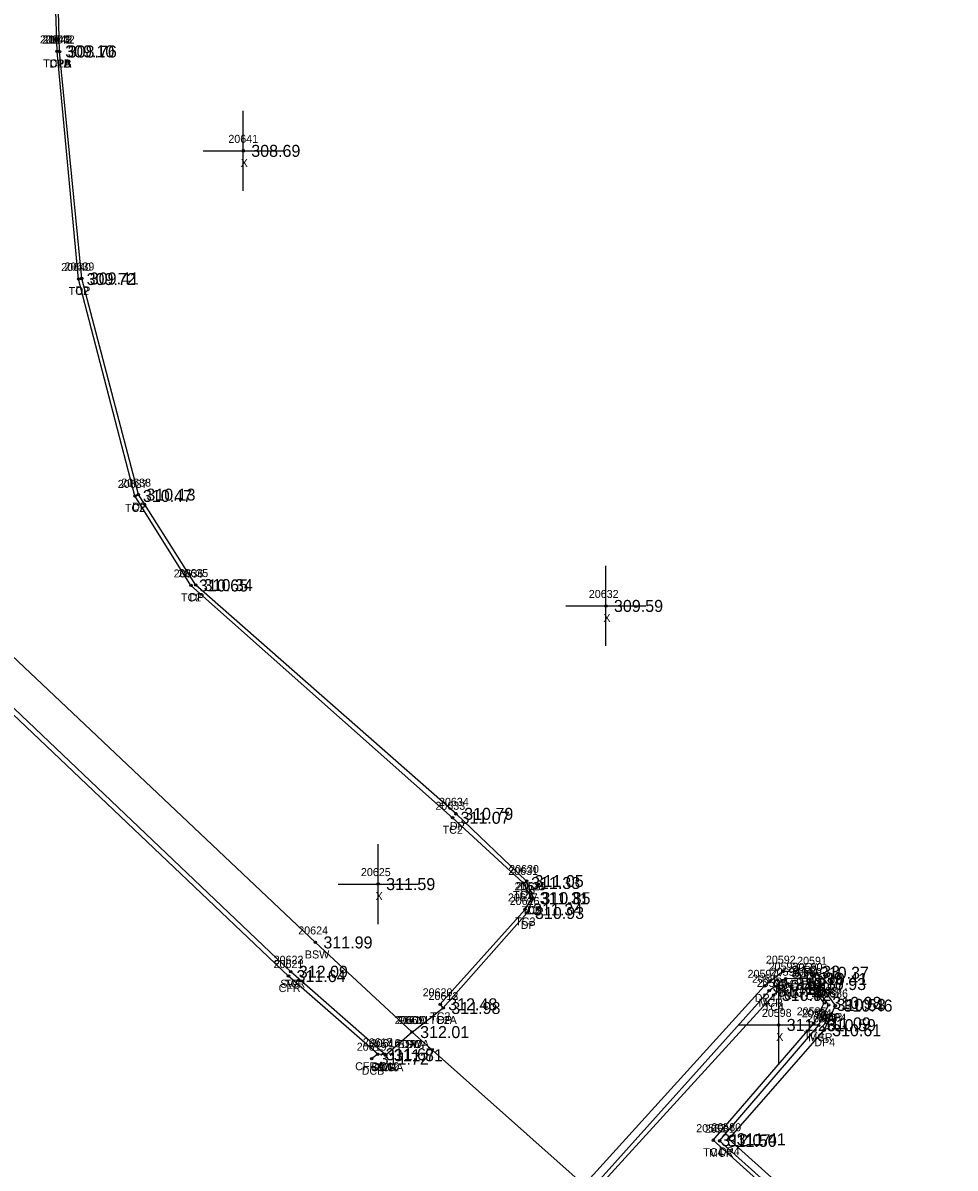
# Model space of a CAD drawing. Extents: x 1970242 to 1971082, y 803104 to 803947.
# Drawn here: x 1970776.8 to 1970893.2, y 803378.4 to 803521.5 of the extents above; entities that cross this region are included whole.
import ezdxf

# ---------------------------------------------------------------- set-up
doc = ezdxf.new("R2010")
doc.units = 0
for name, color, linetype in [('RD_DTM_BkLn2', 7, 'Continuous'), ('RD_EX_Conc', 7, 'Continuous'), ('RD_EX_Conc_txCode', 7, 'Continuous'), ('RD_EX_Driveway', 7, 'Continuous'), ('RD_EX_Driveway_txCode', 7, 'Continuous'), ('RD_EX_Misc', 7, 'Continuous'), ('RD_EX_Misc_txCode', 7, 'Continuous'), ('RD_EX_TX_Conc_ELEV', 7, 'Continuous'), ('RD_EX_TX_Driveway_ELEV', 7, 'Continuous'), ('RD_EX_TX_Misc_ELEV', 7, 'Continuous'), ('RD_SMD_Locator', 7, 'Continuous')]:
    doc.layers.add(name, color=color, linetype=linetype)

msp = doc.modelspace()

# ---------------------------------------------------------------- linework, layer by layer
at = {"layer": 'RD_DTM_BkLn2'}
for points in [[(1970781.1, 803517.91), (1970779.46, 803567.03), (1970782.19, 803572.38), (1970789.89, 803580.76), (1970789.6, 803581.03), (1970802.13, 803596.2), (1970803.32, 803597.02), (1970815.2, 803609.32), (1970835.61, 803622.91), (1970852.19, 803631.84), (1970860.32, 803643.91), (1970861.29, 803649.13), (1970859.64, 803653.18), (1970857.32, 803654.93)], [(1970822.14, 803392.47), (1970810.28, 803402.9), (1970754.12, 803456.32), (1970718.38, 803492.24), (1970714.88, 803495.79), (1970706.38, 803506.76), (1970696.99, 803522.32), (1970690.55, 803536.74), (1970687.04, 803546.39), (1970686.42, 803550.35), (1970686.87, 803560.28)], [(1970829.33, 803398.37), (1970828.94, 803398.83), (1970839.54, 803410.68), (1970840.37, 803412.09), (1970839.29, 803413.99), (1970830.48, 803422.14), (1970797.81, 803451.17), (1970790.81, 803462.36), (1970783.78, 803489.46), (1970781.1, 803517.91)], [(1970979.45, 803348.6), (1970975.44, 803343.74), (1970974.92, 803342.04), (1970975.83, 803340.42), (1970980.81, 803335.86), (1970962.06, 803319.23), (1970959.6, 803321.58), (1970957.93, 803322.04), (1970955.92, 803321.12), (1970943.88, 803309.62), (1970934.75, 803317.27), (1970863.04, 803381.85), (1970875.59, 803396.45), (1970876.91, 803399.01), (1970875, 803401.36), (1970872.33, 803401.4), (1970870.6, 803400), (1970848.18, 803375.38), (1970847.84, 803375.76)]]:
    msp.add_lwpolyline(points, dxfattribs=at)
at = {"layer": 'RD_EX_Conc'}
for points in [[(1970822.14, 803392.47), (1970810.28, 803402.9), (1970754.12, 803456.32), (1970718.38, 803492.24), (1970721.52, 803495.16)], [(1970825.43, 803395.36), (1970813.35, 803406.56), (1970757.19, 803459.64), (1970721.52, 803495.16)], [(1970821.14, 803392.59), (1970809.99, 803402.36), (1970753.68, 803455.87), (1970717.79, 803491.63)], [(1970979.04, 803348.83), (1970974.85, 803344.11), (1970974.24, 803342.07), (1970975.36, 803339.91), (1970979.77, 803335.89), (1970962.36, 803320.13), (1970959.86, 803322.22), (1970957.77, 803322.59), (1970955.64, 803321.59), (1970943.94, 803310.25), (1970935.16, 803317.85), (1970863.83, 803381.77), (1970876.22, 803396.22), (1970877.45, 803398.76), (1970875.12, 803402), (1970872.08, 803402.04), (1970870.03, 803400.53), (1970847.84, 803375.76)], [(1970847.44, 803368.09), (1970847.23, 803370.61), (1970846.91, 803376.25), (1970825.43, 803395.36), (1970822.14, 803392.47), (1970821.14, 803392.59), (1970820.38, 803392.03)]]:
    msp.add_lwpolyline(points, dxfattribs=at)
at = {"layer": 'RD_EX_Driveway'}
for points in [[(1970781.41, 803517.89), (1970780.19, 803566.79), (1970783.09, 803572.02), (1970790.56, 803580.4), (1970803.75, 803596.41), (1970815.3, 803608.83), (1970835.93, 803622.28), (1970852.1, 803631.42), (1970860.94, 803643.71), (1970861.75, 803649.17), (1970862.81, 803650.51), (1970861.9, 803654.38), (1970859.56, 803656.74), (1970855.07, 803659.55), (1970853.81, 803659.78), (1970849.95, 803660.12)], [(1970825.43, 803395.36), (1970829.33, 803398.37), (1970839.78, 803410.24), (1970840.58, 803412.09), (1970839.73, 803414.23), (1970830.93, 803422.63), (1970798.4, 803451.22), (1970791.24, 803462.52), (1970784.17, 803489.53), (1970781.41, 803517.89)], [(1970978.49, 803349.37), (1970974.36, 803344.54), (1970973.43, 803342.01), (1970974.82, 803339.34), (1970978.6, 803335.88), (1970962.13, 803321.3), (1970960.21, 803322.85), (1970957.7, 803323.38), (1970955.12, 803322.32), (1970943.79, 803311.55), (1970935.6, 803318.56), (1970864.97, 803381.97), (1970876.89, 803395.59), (1970878.3, 803398.67), (1970875.35, 803402.77), (1970871.74, 803402.91), (1970869.45, 803401.14), (1970846.9, 803376.22)]]:
    msp.add_lwpolyline(points, dxfattribs=at)
at = {"layer": 'RD_EX_Misc'}
for p, q in [((1970804.34, 803500.48), (1970804.34, 803510.48)), ((1970799.34, 803505.48), (1970809.34, 803505.48)), ((1970849.64, 803443.61), (1970849.64, 803453.61)), ((1970844.64, 803448.61), (1970854.64, 803448.61)), ((1970821.19, 803408.85), (1970821.19, 803418.85)), ((1970816.19, 803413.85), (1970826.19, 803413.85)), ((1970871.22, 803391.26), (1970871.22, 803401.26)), ((1970866.22, 803396.26), (1970876.22, 803396.26))]:
    msp.add_line(p, q, dxfattribs=at)
at = {"layer": 'RD_SMD_Locator'}
for centre in [(1970781.1, 803517.91), (1970781.1, 803517.91), (1970781.41, 803517.89), (1970781.41, 803517.89), (1970804.34, 803505.48), (1970784.17, 803489.53), (1970783.78, 803489.46), (1970790.81, 803462.36), (1970791.24, 803462.52), (1970797.81, 803451.17), (1970798.4, 803451.22), (1970849.64, 803448.61), (1970830.93, 803422.63), (1970830.48, 803422.14), (1970821.19, 803413.85), (1970839.29, 803413.99), (1970839.73, 803414.23), (1970840.37, 803412.09), (1970840.58, 803412.09), (1970839.54, 803410.68), (1970839.78, 803410.24), (1970813.35, 803406.56), (1970809.99, 803402.36), (1970810.28, 803402.9), (1970810.28, 803402.9), (1970871.74, 803402.91), (1970875.35, 803402.77), (1970869.45, 803401.14), (1970872.08, 803402.04), (1970872.33, 803401.4), (1970875, 803401.36), (1970875.12, 803402), (1970870.03, 803400.53), (1970870.6, 803400), (1970828.94, 803398.83), (1970829.33, 803398.37), (1970829.33, 803398.37), (1970876.91, 803399.01), (1970877.45, 803398.76), (1970878.3, 803398.67), (1970825.43, 803395.36), (1970825.43, 803395.36), (1970825.43, 803395.36), (1970871.22, 803396.26), (1970875.59, 803396.45), (1970876.22, 803396.22), (1970876.89, 803395.59), (1970821.14, 803392.59), (1970821.14, 803392.59), (1970822.14, 803392.47), (1970822.14, 803392.47), (1970822.14, 803392.47), (1970820.38, 803392.03), (1970863.04, 803381.85), (1970863.83, 803381.77), (1970864.97, 803381.97)]:
    msp.add_circle(centre, 0.15, dxfattribs=at)

# ---------------------------------------------------------------- texts
at = {"layer": 'RD_EX_Conc_txCode'}
for s, p in [('20643', (1970778.95, 803518.91)), ('21043', (1970779.26, 803518.91)), ('TC2A', (1970779.36, 803515.91)), ('TC2B', (1970779.38, 803515.91)), ('20640', (1970781.6, 803490.46)), ('TC2', (1970782.54, 803487.46)), ('20637', (1970788.67, 803463.36)), ('TC2', (1970789.57, 803460.36)), ('20636', (1970795.65, 803452.17)), ('TC2', (1970796.57, 803449.17)), ('20633', (1970828.34, 803423.14)), ('TC2', (1970829.24, 803420.14)), ('20631', (1970837.44, 803414.99)), ('20628', (1970838.23, 803413.09)), ('20627', (1970837.4, 803411.68)), ('TC2', (1970838.05, 803411.99)), ('TC2', (1970839.13, 803410.09)), ('TC2', (1970838.3, 803408.68)), ('20624', (1970811.21, 803407.56)), ('BSW', (1970812.04, 803404.56)), ('20621', (1970808.13, 803403.36)), ('20622', (1970808.14, 803403.9)), ('20623', (1970808.14, 803403.9)), ('20593', (1970869.96, 803403.04)), ('20590', (1970872.96, 803403)), ('20596', (1970867.89, 803401.53)), ('20594', (1970870.21, 803402.4)), ('20589', (1970872.88, 803402.36)), ('CFR', (1970808.76, 803400.36)), ('SWR', (1970808.97, 803400.9)), ('TC', (1970809.49, 803400.9)), ('20595', (1970868.48, 803401)), ('MCR', (1970870.77, 803400.04)), ('MCR', (1970873.8, 803400)), ('20588', (1970874.79, 803400.01)), ('20620', (1970826.75, 803399.83)), ('20613', (1970827.48, 803399.37)), ('MCR', (1970868.71, 803398.53)), ('TC4', (1970871.08, 803399.4)), ('TC4', (1970873.76, 803399.36)), ('20587', (1970875.33, 803399.76)), ('TC4', (1970869.35, 803398)), ('20585', (1970873.47, 803397.45)), ('20584', (1970874.1, 803397.22)), ('20609', (1970823.25, 803396.36)), ('20611', (1970823.86, 803396.36)), ('TC2A', (1970827.6, 803396.37)), ('TC2', (1970827.69, 803396.83)), ('TC4', (1970875.66, 803397.01)), ('MCR', (1970876.13, 803396.76)), ('TC4', (1970874.35, 803394.45)), ('MCR', (1970874.91, 803394.22)), ('20619', (1970818.52, 803393.03)), ('20617', (1970819.28, 803393.59)), ('20618', (1970819.28, 803393.59)), ('20616', (1970820.25, 803393.47)), ('20614', (1970820.28, 803393.47)), ('20615', (1970820.28, 803393.47)), ('BSWA', (1970823.63, 803393.36)), ('DC', (1970824.65, 803393.36)), ('CFRA 12', (1970818.32, 803390.59)), ('DCB', (1970819.13, 803390.03)), ('SWRA', (1970820.33, 803390.47)), ('DC', (1970820.36, 803390.59)), ('TCA', (1970820.85, 803390.47)), ('DC', (1970821.36, 803390.47)), ('20582', (1970860.92, 803382.85)), ('20581', (1970862, 803382.77)), ('TC4', (1970861.79, 803379.85)), ('MCR', (1970862.52, 803379.77))]:
    msp.add_text(s, height=1, dxfattribs=at).set_placement(p)
at = {"layer": 'RD_EX_Driveway_txCode'}
for s, p in [('20642', (1970779.26, 803518.89)), ('21042', (1970779.57, 803518.89)), ('DPA', (1970780.14, 803515.89)), ('DPB', (1970780.15, 803515.89)), ('20639', (1970782.02, 803490.53)), ('DP', (1970783.39, 803487.53)), ('20638', (1970789.1, 803463.52)), ('DP', (1970790.46, 803460.52)), ('20635', (1970796.25, 803452.22)), ('DP', (1970797.62, 803449.22)), ('20634', (1970828.79, 803423.63)), ('DP', (1970830.15, 803420.63)), ('20630', (1970837.55, 803415.23)), ('20629', (1970838.43, 803413.09)), ('DP', (1970838.95, 803412.23)), ('20626', (1970837.62, 803411.24)), ('DP', (1970839.8, 803410.09)), ('DP', (1970839, 803408.24)), ('20592', (1970869.62, 803403.91)), ('20591', (1970873.52, 803403.77)), ('20597', (1970867.33, 803402.14)), ('DP4', (1970870.51, 803400.91)), ('DP4', (1970874.12, 803400.77)), ('20612', (1970827.48, 803399.37)), ('DP4', (1970868.22, 803399.14)), ('20586', (1970876.15, 803399.67)), ('20610', (1970823.53, 803396.36)), ('DP', (1970828.55, 803396.37)), ('20583', (1970874.78, 803396.59)), ('DP4', (1970877.07, 803396.67)), ('DPA', (1970824.16, 803393.36)), ('DP4', (1970875.67, 803393.59)), ('20580', (1970862.81, 803382.97)), ('DP4', (1970863.74, 803379.97))]:
    msp.add_text(s, height=1, dxfattribs=at).set_placement(p)
at = {"layer": 'RD_EX_Misc_txCode'}
for s, p in [('20641', (1970802.48, 803506.48)), ('X', (1970804.02, 803503.48)), ('20632', (1970847.5, 803449.61)), ('X', (1970849.33, 803446.61)), ('20625', (1970819.04, 803414.85)), ('X', (1970820.87, 803411.85)), ('20598', (1970869.11, 803397.26)), ('X', (1970870.91, 803394.26))]:
    msp.add_text(s, height=1, dxfattribs=at).set_placement(p)
at = {"layer": 'RD_EX_TX_Conc_ELEV'}
for s, p in [('309.10', (1970782.1, 803517.16)), ('309.10', (1970782.1, 803517.16)), ('309.72', (1970784.78, 803488.71)), ('310.47', (1970791.81, 803461.61)), ('310.65', (1970798.81, 803450.42)), ('311.07', (1970831.48, 803421.39)), ('311.33', (1970840.29, 803413.24)), ('311.31', (1970841.37, 803411.34)), ('311.34', (1970840.54, 803409.93)), ('311.99', (1970814.35, 803405.81)), ('311.64', (1970810.99, 803401.61)), ('312.09', (1970811.28, 803402.15)), ('312.09', (1970811.28, 803402.15)), ('310.39', (1970873.08, 803401.29)), ('310.41', (1970876.12, 803401.25)), ('310.45', (1970871.03, 803399.78)), ('310.87', (1970873.33, 803400.65)), ('310.93', (1970876, 803400.61)), ('312.48', (1970829.94, 803398.08)), ('310.92', (1970871.6, 803399.25)), ('310.98', (1970877.91, 803398.26)), ('310.53', (1970878.45, 803398.01)), ('311.98', (1970830.33, 803397.62)), ('311.09', (1970876.59, 803395.7)), ('310.59', (1970877.22, 803395.47)), ('312.01', (1970826.43, 803394.61)), ('312.01', (1970826.43, 803394.61)), ('311.72', (1970821.38, 803391.28)), ('311.67', (1970822.14, 803391.84)), ('311.67', (1970822.14, 803391.84)), ('311.81', (1970823.14, 803391.72)), ('311.81', (1970823.14, 803391.72)), ('311.81', (1970823.14, 803391.72)), ('312.07', (1970864.04, 803381.1)), ('311.50', (1970864.83, 803381.02))]:
    msp.add_text(s, height=1.5, dxfattribs=at).set_placement(p)
at = {"layer": 'RD_EX_TX_Driveway_ELEV'}
for s, p in [('308.76', (1970782.41, 803517.14)), ('308.76', (1970782.41, 803517.14)), ('309.41', (1970785.17, 803488.78)), ('310.13', (1970792.24, 803461.77)), ('310.34', (1970799.4, 803450.47)), ('310.79', (1970831.93, 803421.88)), ('311.05', (1970840.73, 803413.48)), ('310.85', (1970841.58, 803411.34)), ('310.93', (1970840.78, 803409.49)), ('310.33', (1970872.74, 803402.16)), ('310.37', (1970876.35, 803402.02)), ('310.48', (1970870.45, 803400.39)), ('311.98', (1970830.33, 803397.62)), ('310.46', (1970879.3, 803397.92)), ('312.01', (1970826.43, 803394.61)), ('310.61', (1970877.89, 803394.84)), ('311.41', (1970865.97, 803381.22))]:
    msp.add_text(s, height=1.5, dxfattribs=at).set_placement(p)
at = {"layer": 'RD_EX_TX_Misc_ELEV'}
for s, p in [('308.69', (1970805.34, 803504.73)), ('309.59', (1970850.64, 803447.86)), ('311.59', (1970822.19, 803413.1)), ('311.26', (1970872.22, 803395.51))]:
    msp.add_text(s, height=1.5, dxfattribs=at).set_placement(p)

doc.saveas('drawing.dxf')
